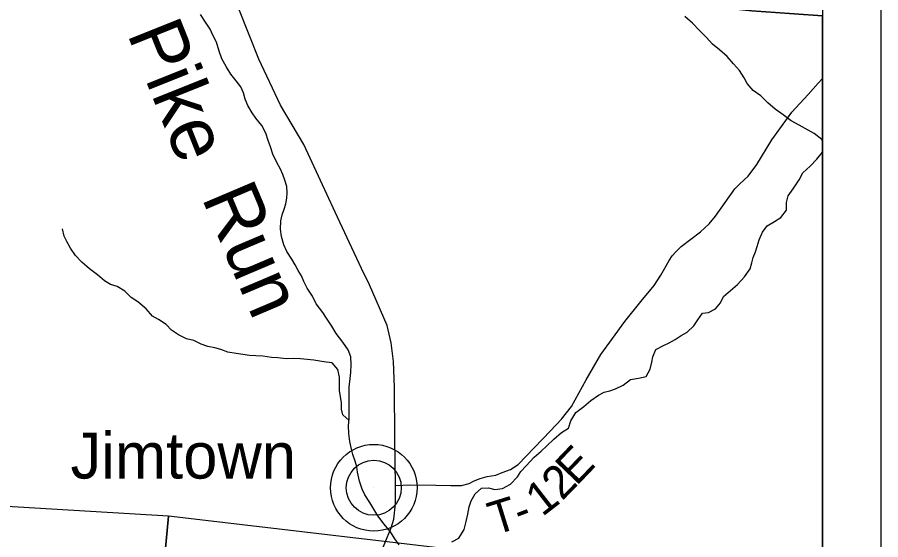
# Model space of a CAD drawing. Extents: x -13.1 to 43.1, y 0 to 22.
# Drawn here: x 7.517 to 9, y 14.849 to 15.746 of the extents above; entities that cross this region are included whole.
import ezdxf

# ---------------------------------------------------------------- set-up
doc = ezdxf.new("R2010")
doc.units = 0
for name, color, linetype in [('GM_X_Corporation', 7, 'Continuous'), ('GM_X_Minor_River', 7, 'Continuous'), ('GM_X_Minor_River_Text', 7, 'Continuous'), ('GM_X_State_Route', 7, 'Continuous'), ('GM_X_Township_Road', 7, 'Continuous'), ('GM_X_Township_Road_Text', 7, 'Continuous'), ('GM_X_Unincorporated', 7, 'Continuous'), ('GM_X_Unincorporated_Location', 7, 'Continuous'), ('GM_X_Unincorporated_Text', 7, 'Continuous'), ('SH_Data', 7, 'Continuous')]:
    doc.layers.add(name, color=color, linetype=linetype)

msp = doc.modelspace()

# ---------------------------------------------------------------- linework, layer by layer
at = {"layer": 'GM_X_Corporation'}
for points in [[(6.619, 14.1), (8.9, 14.1), (8.9, 15.7487), (8.7782, 15.7572), (7.8612, 15.855), (6.7528, 15.9566), (6.6992, 15.2074)], [(6.619, 14.1), (8.9, 14.1), (8.9, 15.7487), (8.7782, 15.7572), (7.8612, 15.855), (6.7528, 15.9566), (6.6992, 15.2074)], [(6.6193, 14.1), (8.9, 14.1), (8.9, 15.7481), (8.7784, 15.7567), (7.8614, 15.8545), (6.7531, 15.956), (6.6994, 15.2069)], [(6.623, 14.1), (7.7024, 14.1), (7.7762, 14.8894), (6.6851, 14.9543)], [(7.7024, 14.1), (8.6942, 14.1), (8.7515, 14.7745), (7.7762, 14.8894)]]:
    msp.add_lwpolyline(points, close=True, dxfattribs=at)
at = {"layer": 'GM_X_Minor_River'}
for points in [[(8.1724, 14.8399), (8.1652, 14.8501), (8.1576, 14.8623), (8.1471, 14.8756), (8.1361, 14.89), (8.1289, 14.9014), (8.1221, 14.9127), (8.1134, 14.9256), (8.1089, 14.9355), (8.1043, 14.9495), (8.1013, 14.9647), (8.0998, 14.9742), (8.0968, 14.9836), (8.093, 14.995), (8.0907, 15.0045), (8.0881, 15.0174), (8.0862, 15.031), (8.0858, 15.0443), (8.087, 15.0568), (8.087, 15.0693), (8.0866, 15.0788), (8.087, 15.0906), (8.087, 15.1008), (8.087, 15.111), (8.0882, 15.1258), (8.0897, 15.1361), (8.0904, 15.1497), (8.0897, 15.1626), (8.0848, 15.1747), (8.0761, 15.188), (8.0647, 15.2028), (8.0568, 15.2157), (8.0481, 15.2293), (8.0413, 15.2392), (8.0303, 15.254), (8.0235, 15.2669), (8.0144, 15.2806), (8.0088, 15.2923), (8.005, 15.3018), (7.9993, 15.3113), (7.994, 15.3211), (7.9884, 15.3306), (7.9797, 15.3439), (7.9747, 15.3553), (7.9706, 15.3697), (7.9687, 15.3822), (7.9695, 15.3962), (7.9717, 15.4068), (7.9752, 15.4163), (7.9782, 15.4258), (7.9797, 15.4353), (7.9805, 15.4447), (7.9797, 15.4554), (7.9763, 15.4664), (7.9729, 15.4758), (7.9688, 15.4853), (7.9627, 15.4967), (7.9555, 15.5107), (7.9517, 15.5232), (7.9476, 15.5342), (7.9434, 15.5471), (7.9366, 15.56), (7.9264, 15.5725), (7.9204, 15.582), (7.9128, 15.5945), (7.9079, 15.6052), (7.9052, 15.6162), (7.9007, 15.6264), (7.8924, 15.6366), (7.8837, 15.6484), (7.8754, 15.6613), (7.8678, 15.6746), (7.8637, 15.6875), (7.8587, 15.7034), (7.8523, 15.7155), (7.8478, 15.7254), (7.841, 15.7356), (7.8315, 15.7508)], [(8.9, 15.533), (8.8986, 15.5362), (8.8854, 15.5461), (8.8596, 15.5605), (8.846, 15.5681), (8.8324, 15.5787), (8.8188, 15.5882), (8.8059, 15.5992), (8.7938, 15.611), (8.781, 15.6205), (8.7704, 15.6322), (8.7655, 15.6421), (8.7571, 15.6546), (8.7473, 15.666), (8.736, 15.6785), (8.7231, 15.6899), (8.711, 15.6997), (8.7, 15.7119), (8.6887, 15.7233), (8.6766, 15.7358), (8.6633, 15.7472)], [(8.2632, 14.8451), (8.275, 14.8516), (8.2844, 14.8664), (8.2875, 14.88), (8.2909, 14.8925), (8.2928, 14.9054), (8.2962, 14.9153), (8.3034, 14.9274), (8.3144, 14.9372), (8.3261, 14.938), (8.3371, 14.9349), (8.3503, 14.9368), (8.3639, 14.9444), (8.3757, 14.9565), (8.3817, 14.966), (8.3908, 14.9755), (8.4045, 14.9906), (8.4166, 15.0009), (8.4264, 15.0099), (8.4385, 15.0217), (8.4518, 15.0331), (8.4635, 15.0402), (8.4677, 15.0531), (8.4764, 15.0672), (8.4897, 15.0778), (8.5021, 15.088), (8.515, 15.0971), (8.5249, 15.102), (8.5347, 15.1043), (8.5445, 15.1077), (8.5574, 15.1141), (8.5703, 15.124), (8.5839, 15.1262), (8.5968, 15.1289), (8.604, 15.1418), (8.6066, 15.1535), (8.6085, 15.163), (8.6138, 15.1755), (8.6267, 15.1823), (8.6365, 15.1868), (8.6468, 15.1929), (8.657, 15.1993), (8.6676, 15.205), (8.6789, 15.216), (8.6858, 15.2262), (8.6937, 15.2376), (8.7039, 15.2391), (8.7161, 15.2455), (8.7248, 15.2558), (8.7301, 15.2664), (8.7418, 15.277), (8.7539, 15.2872), (8.7657, 15.3005), (8.7759, 15.3137), (8.7785, 15.324), (8.7808, 15.3335), (8.7846, 15.3429), (8.7876, 15.3524), (8.791, 15.3638), (8.7967, 15.3767), (8.8047, 15.388), (8.8175, 15.3952), (8.8285, 15.4024), (8.838, 15.4145), (8.838, 15.4278), (8.841, 15.4392), (8.8497, 15.4513), (8.86, 15.4669), (8.8664, 15.479), (8.8785, 15.4903), (8.8903, 15.5021), (8.9, 15.5146)], [(8.0867, 15.0535), (8.076, 15.0633), (8.0737, 15.0728), (8.0734, 15.0841), (8.0719, 15.0947), (8.07, 15.1046), (8.0704, 15.1179), (8.07, 15.1277), (8.0673, 15.141), (8.0575, 15.1524), (8.0473, 15.1539), (8.0363, 15.1554), (8.0261, 15.157), (8.0148, 15.1585), (8.003, 15.1592), (7.9913, 15.16), (7.9788, 15.1593), (7.964, 15.1612), (7.9531, 15.1616), (7.9387, 15.1638), (7.9266, 15.1646), (7.9156, 15.1654), (7.9043, 15.1669), (7.8925, 15.1684), (7.8781, 15.1711), (7.8664, 15.1756), (7.8558, 15.1783), (7.8437, 15.1806), (7.8327, 15.1848), (7.8199, 15.1908), (7.8074, 15.1935), (7.7938, 15.2007), (7.7817, 15.2087), (7.7722, 15.2186), (7.7593, 15.2269), (7.7491, 15.2326), (7.7382, 15.2451), (7.7238, 15.2573), (7.7121, 15.2649), (7.7011, 15.2759), (7.6882, 15.2838), (7.6769, 15.2872), (7.6663, 15.2933), (7.6542, 15.3039), (7.6406, 15.3138), (7.6277, 15.3252), (7.6164, 15.3366), (7.608, 15.3495), (7.602, 15.3608), (7.5974, 15.3703), (7.5944, 15.3825)]]:
    msp.add_lwpolyline(points, dxfattribs=at)
at = {"layer": 'GM_X_State_Route'}
msp.add_lwpolyline([(8.1369, 14.8166), (8.1591, 14.8691), (8.1634, 14.884), (8.1663, 14.9105), (8.1666, 14.942), (8.1654, 15.0225), (8.1645, 15.1105), (8.1627, 15.155), (8.1589, 15.1867), (8.152, 15.2168), (8.1215, 15.2866), (8.1082, 15.3148), (8.063, 15.4115), (8.0483, 15.4421), (8.0087, 15.5276), (7.9686, 15.5952), (7.9313, 15.674), (7.8962, 15.7631), (7.8614, 15.8545)], dxfattribs=at)
at = {"layer": 'GM_X_Township_Road'}
msp.add_lwpolyline([(8.1666, 14.942), (8.1912, 14.9428), (8.2355, 14.9426), (8.2612, 14.9419), (8.2795, 14.9421), (8.2927, 14.9451), (8.3017, 14.9497), (8.3119, 14.9537), (8.3237, 14.9572), (8.3388, 14.9599), (8.3499, 14.9642), (8.3638, 14.9692), (8.377, 14.9782), (8.4324, 15.0355), (8.4518, 15.0556), (8.4687, 15.0776), (8.4938, 15.1233), (8.5192, 15.1668), (8.5389, 15.1946), (8.5602, 15.2238), (8.5887, 15.2585), (8.6105, 15.2856), (8.6223, 15.3032), (8.6293, 15.3153), (8.6367, 15.3285), (8.6418, 15.3364), (8.6487, 15.344), (8.6573, 15.3521), (8.6902, 15.3774), (8.705, 15.3915), (8.7159, 15.4047), (8.7493, 15.4513), (8.7581, 15.4598), (8.7722, 15.4733), (8.7872, 15.4932), (8.813, 15.5354), (8.8294, 15.5585), (8.8475, 15.5831), (8.8751, 15.6133), (8.8927, 15.6327), (8.9, 15.6407)], dxfattribs=at)
at = {"layer": 'GM_X_Unincorporated'}
for radius in [0.0744, 0.0472]:
    msp.add_circle((8.1291, 14.938), radius, dxfattribs=at)
at = {"layer": 'GM_X_Unincorporated_Location'}
msp.add_line((8.1291, 14.938), (8.1291, 14.938), dxfattribs=at)
at = {"layer": 'SH_Data'}
for p, q in [((9, 21), (9, 14)), ((8.9, 20.9), (8.9, 14.1))]:
    msp.add_line(p, q, dxfattribs=at)

# ---------------------------------------------------------------- texts
at = {"layer": 'GM_X_Minor_River_Text'}
for s, rotation, p in [('Pike', 291.8076, (7.7047, 15.7183)), ('Run', 292.9753, (7.8326, 15.4367))]:
    msp.add_text(s, height=0.0947, rotation=rotation, dxfattribs=at).set_placement(p)
at = {"layer": 'GM_X_Township_Road_Text'}
for s, rotation, p in [('E', 46.1723, (8.477, 14.9398)), ('2', 45.9091, (8.4525, 14.9145)), ('1', 37.8277, (8.4184, 14.8872)), ('T', 17.283, (8.3364, 14.8561)), ('-', 20.8197, (8.3806, 14.8699))]:
    msp.add_text(s, height=0.0568, rotation=rotation, dxfattribs=at).set_placement(p)
at = {"layer": 'GM_X_Unincorporated_Text'}
msp.add_text('Jimtown', height=0.07898, rotation=0, dxfattribs=at).set_placement((7.6081, 14.9538))

doc.saveas('drawing.dxf')
